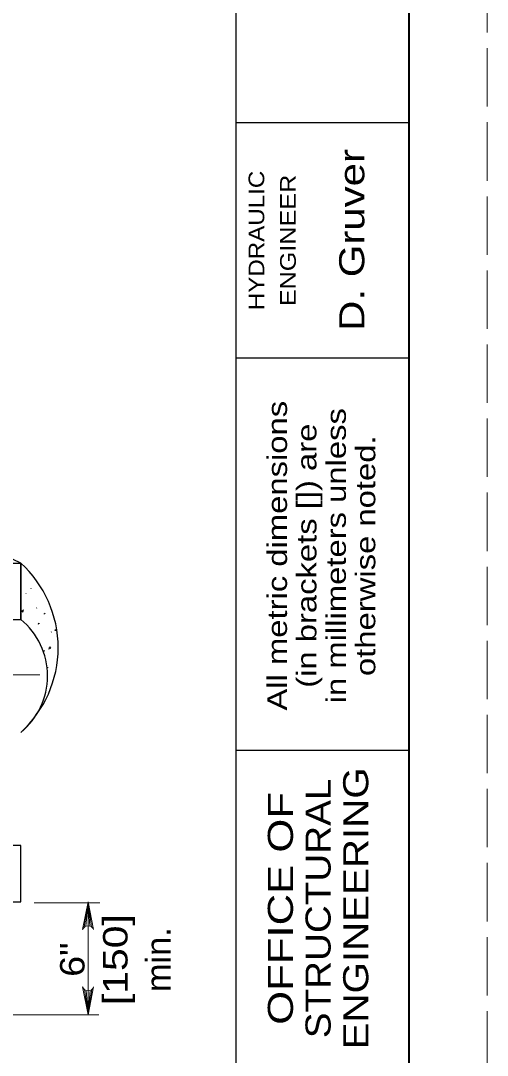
# Model space of a CAD drawing. Extents: x 1083.1 to 1117.1, y 697.4 to 741.4.
# Drawn here: x 1114.15 to 1117.13, y 728.41 to 735.01 of the extents above; entities that cross this region are included whole.
import ezdxf
from ezdxf.enums import TextEntityAlignment as Align

# ---------------------------------------------------------------- set-up
doc = ezdxf.new("R2010")
doc.units = 0
doc.header["$LTSCALE"] = 0.062
doc.linetypes.add('LONG_DASHED', pattern=[7.5, 6, -1.5])
doc.layers.add('1', color=7, linetype='Continuous', lineweight=13)

msp = doc.modelspace()

# ---------------------------------------------------------------- linework, layer by layer
at = {"layer": '1', "lineweight": 25}
for p, q in [((1115.52642, 719.85408), (1115.52642, 740.85408)), ((1116.62642, 740.85408), (1116.62642, 719.85408)), ((1116.62642, 734.35408), (1115.52642, 734.35408)), ((1116.62642, 732.85408), (1115.52642, 732.85408)), ((1114.15358, 731.18967), (1114.15358, 731.5495)), ((1114.15358, 731.5495), (1114.15358, 731.18967)), ((1116.62642, 730.35408), (1115.52642, 730.35408)), ((1114.15358, 729.7505), (1109.69433, 729.7505)), ((1114.15358, 729.39075), (1114.15358, 729.7505)), ((1112.64358, 729.39075), (1114.15358, 729.39075))]:
    msp.add_line(p, q, dxfattribs=at)
at = {"layer": '1'}
for p, q in [((1114.21858, 731.386), (1114.21942, 731.38842)), ((1114.18833, 731.35642), (1114.18642, 731.35492)), ((1114.25567, 731.26492), (1114.25467, 731.26258)), ((1114.34892, 731.11142), (1114.348, 731.10908)), ((1114.3295, 730.884), (1114.32725, 730.88317)), ((1113.95033, 730.83783), (1114.27458, 730.83783)), ((1114.23975, 729.384), (1114.65842, 729.384)), ((1114.55792, 729.22858), (1114.58275, 729.39075)), ((1114.56833, 729.23475), (1114.58275, 729.39075)), ((1114.58275, 728.67117), (1114.58275, 729.39075)), ((1114.58275, 729.23758), (1114.58275, 729.39075)), ((1114.59408, 729.23592), (1114.58275, 729.39075)), ((1114.60517, 729.2305), (1114.58275, 729.39075)), ((1114.56033, 728.83142), (1114.58275, 728.67117)), ((1114.57142, 728.82592), (1114.58275, 728.67117)), ((1114.6075, 728.83325), (1114.58275, 728.67117)), ((1114.59708, 728.82717), (1114.58275, 728.67117)), ((1114.58275, 728.82433), (1114.58275, 728.67117)), ((1112.73908, 728.67117), (1114.65142, 728.67117))]:
    msp.add_line(p, q, dxfattribs=at)
at = {"layer": '1', "linetype": 'LONG_DASHED'}
msp.add_lwpolyline([(1083.12642, 719.35408), (1117.12642, 719.35408), (1117.12642, 741.35408), (1083.12642, 741.35408)], close=True, dxfattribs=at)
at = {"layer": '1', "lineweight": 40}
msp.add_lwpolyline([(1085.12642, 740.85408), (1116.62642, 740.85408), (1116.62642, 719.85408), (1085.12642, 719.85408)], close=True, dxfattribs=at)
msp.add_lwpolyline([(1085.12642, 740.85408), (1116.62642, 740.85408), (1116.62642, 719.85408), (1085.12642, 719.85408)], close=True, dxfattribs=at)
at = {"layer": '1', "lineweight": 25}
for points in [[(1111.92392, 731.5495), (1114.15358, 731.5495), (1112.64358, 732.26908)], [(1109.69433, 731.30958), (1109.69433, 731.18967), (1114.15358, 731.18967)]]:
    msp.add_lwpolyline(points, dxfattribs=at)
at = {"layer": '1'}
for points in [[(1114.16725, 731.23608), (1114.17158, 731.25025), (1114.15917, 731.24558), (1114.167, 731.23633)], [(1114.30842, 731.22942), (1114.30675, 731.22875), (1114.30167, 731.22283)], [(1114.30483, 730.99133), (1114.30408, 730.98967), (1114.29808, 730.98458)], [(1114.338, 731.01583), (1114.33375, 731.00167), (1114.34592, 731.00633), (1114.33817, 731.01558)], [(1114.54733, 729.21375), (1114.58275, 729.39075), (1114.61817, 729.21375)], [(1114.61817, 728.84817), (1114.58275, 728.67117), (1114.54733, 728.84817)]]:
    msp.add_lwpolyline(points, dxfattribs=at)
for points in [[(1114.273, 731.16417), (1114.26633, 731.16658), (1114.26533, 731.16017)], [(1114.3745, 731.1265), (1114.37675, 731.11975), (1114.3705, 731.11892)]]:
    msp.add_lwpolyline(points, close=True, dxfattribs=at)
for centre, start, end in [((1114.58277, 729.19943), 22.08782, 157.91395), ((1114.58269, 728.86243), 202.08782, 337.91395)]:
    msp.add_arc(centre, 0.0382, start, end, dxfattribs=at)
at = {"layer": '1', "lineweight": 25}
for centre, major_axis, start_param, end_param in [((1113.66342, 731.00979), (0.72908, 0), 5.4496588, 7.1167118), ((1113.66342, 731.00979), (0.72908, 0), 5.4496588, 7.1167118), ((1113.86053, 730.8299), (0.46406, 0), 5.3958304, 7.1705402), ((1113.86053, 730.8299), (0.46406, 0), 5.3958304, 7.1705402)]:
    msp.add_ellipse(centre, major_axis=major_axis, ratio=0.999895, start_param=start_param, end_param=end_param, dxfattribs=at)

# ---------------------------------------------------------------- texts
at = {"layer": '1'}
for s, height, width, p in [('D. Gruver', 0.16, 1.25, (1116.34283, 733.60825)), ('HYDRAULIC', 0.1, 1.15, (1115.7055, 733.60517)), ('ENGINEER', 0.1, 1.2, (1115.90642, 733.60521)), ('All metric dimensions', 0.125, 1.25, (1115.85025, 731.59617)), ('in millimeters unless', 0.125, 1.25, (1116.22525, 731.59621)), ('(in brackets []) are', 0.125, 1.25, (1116.03775, 731.59617)), ('otherwise noted.', 0.125, 1.25, (1116.41275, 731.59617)), ('ENGINEERING', 0.16, 1.2, (1116.36817, 729.34862)), ('STRUCTURAL', 0.16, 1.15, (1116.12817, 729.34854)), ('OFFICE OF', 0.16, 1.3, (1115.88817, 729.34854)), ('[150]', 0.156, 1.25, (1114.83417, 729.022)), ('min.', 0.156, 1.05, (1115.10817, 729.022)), ('6"', 0.156, 1.15, (1114.56017, 729.022))]:
    msp.add_text(s, height=height, rotation=90, dxfattribs=dict(at, width=width)).set_placement(p, align=Align.CENTER)

doc.saveas('drawing.dxf')
